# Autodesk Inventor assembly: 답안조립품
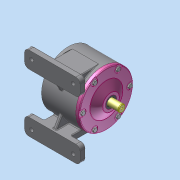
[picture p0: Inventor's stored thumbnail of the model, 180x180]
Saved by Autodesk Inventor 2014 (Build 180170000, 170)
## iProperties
Created: 2026-04
Part Number: 답안조립품
Document SubType Name: Assembly
Designer: dg
Author: dg
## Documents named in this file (17)
- C:\Users\dg\Desktop\660403V1010\답안조립품.iam
- C:\Users\dg\Desktop\660403V1010\가져온 구성요소\본체\본체.ipt
- C:\Users\dg\Desktop\660403V1010\가져온 구성요소\깊은 홈 볼 베어링 6004\깊은 홈 볼 베어링 6004.ipt
- C:\Users\dg\Desktop\660403V1010\가져온 구성요소\기어 축\기어 축.ipt
- C:\Users\dg\Desktop\660403V1010\가져온 구성요소\C형 멈춤링 구멍용 42\C형 멈춤링 구멍용 42.ipt
- C:\Users\dg\Desktop\660403V1010\가져온 구성요소\칼라 1\칼라 1.ipt
- C:\Users\dg\Desktop\660403V1010\가져온 구성요소\평행 키 6x6x16\평행 키 6x6x16.ipt
- C:\Users\dg\Desktop\660403V1010\가져온 구성요소\구동 기어\구동 기어.ipt
- C:\Users\dg\Desktop\660403V1010\가져온 구성요소\엔드 캡\엔드 캡.ipt
- C:\Users\dg\Desktop\660403V1010\가져온 구성요소\6각 구멍붙이 볼트 M4x10\6각 구멍붙이 볼트 M4x10.ipt
- C:\Users\dg\Desktop\660403V1010\가져온 구성요소\출력 축\출력 축.ipt
- C:\Users\dg\Desktop\660403V1010\가져온 구성요소\종동 기어\종동 기어.ipt
- C:\Users\dg\Desktop\660403V1010\가져온 구성요소\칼라 2\칼라 2.ipt
- C:\Users\dg\Desktop\660403V1010\가져온 구성요소\커버\커버.ipt
- C:\Users\dg\Desktop\660403V1010\가져온 구성요소\깊은 홈 볼 베어링 6005\깊은 홈 볼 베어링 6005.ipt
- C:\Users\dg\Desktop\660403V1010\가져온 구성요소\오일 실 25 40 8\오일 실 25 40 8.ipt
- C:\Users\dg\Desktop\660403V1010\가져온 구성요소\6각 머리 볼트 M8x20\6각 머리 볼트 M8x20.ipt
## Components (9 placed, 4 different names)
1. C형 멈춤링 구멍용 42:1
2. 구동 기어:1
3. 6각 구멍붙이 볼트 M4x10:1
4. 6각 머리 볼트 M8x20:1
5. 6각 머리 볼트 M8x20:2
6. 6각 머리 볼트 M8x20:3
7. 6각 머리 볼트 M8x20:4
8. 6각 머리 볼트 M8x20:5
9. 6각 머리 볼트 M8x20:6
